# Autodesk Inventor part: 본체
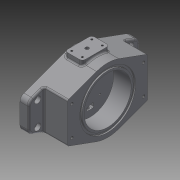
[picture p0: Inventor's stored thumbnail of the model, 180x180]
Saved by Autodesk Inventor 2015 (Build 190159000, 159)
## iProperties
Created: 2023-11
Part Number: 본체
Material: 알루미늄 6061
Document SubType Name: Modeling
Designer: user
Density: 2.7 g/cm^3
Appearance: 기본값
Mass: 1561.22 g
Surface Area: 721.057 cm^2
Volume: 578.228 cm^3
Author: user
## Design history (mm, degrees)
sketch "스케치2"
  geometry: L1 (18.811, 51.683)-(94, 24.317); L2 (94, 24.317)-(94, -24.317); L3 (18.811, -51.683)-(94, -24.317); L4 (0, 0)-(66.664, 0); L5 (0, 55)-(0, -55); L6 (-18.811, 51.683)-(-94, 24.317); L7 (-94, 24.317)-(-94, -24.317); L8 (-18.811, -51.683)-(-94, -24.317); A1 r 55 centre (0, 0) between (18.811, 51.683) and (-18.811, 51.683); A2 r 55 centre (0, 0) between (-18.811, -51.683) and (18.811, -51.683); 1 further point
  constraints: 16 end point, 6 point on circle, 4 symmetric about line, 2 centre point, 2 tangent, 2 vertical, 1 coincident, 1 horizontal, 1 other
  dimensions: "d3" = 94 distance from line of point (0, 0) L2; "d4" = 40 deg angle of L1 L3; "d5" = 55 radius of A1
extrude "돌출1" new body sketch "스케치2" distance "d6" = 15; taper "d7" = 0 deg
sketch "스케치4"
  geometry: L1 (-24.317, 94)-(-51.683, 18.811) reference; L2 (-51.683, -18.811)-(-24.317, -94) reference; L3 (-24.317, -94)-(24.317, -94) reference; L4 (51.683, 18.811)-(24.317, 94) reference; L5 (24.317, 94)-(-24.317, 94) reference; L6 (51.683, -18.811)-(24.317, -94) reference; L7 (-33.78, 68)-(33.78, 68); L8 (-33.78, 68)-(-51.683, 18.811); L9 (33.78, 68)-(51.683, 18.811); L10 (-33.78, -68)-(33.78, -68); L11 (-33.78, -68)-(-51.683, -18.811); L12 (-24.317, -94)-(-51.683, -18.811) reference; L13 (33.78, -68)-(51.683, -18.811); A1 r 55 centre (0, 0) between (-51.683, 18.811) and (-51.683, -18.811) reference; A2 r 55 centre (0, 0) between (51.683, -18.811) and (51.683, 18.811) reference; A3 r 55 centre (0, 0) between (-51.683, 18.811) and (-51.683, -18.811); A4 r 55 centre (0, 0) between (51.683, -18.811) and (51.683, 18.811)
  constraints: 13 end point, 4 point on circle, 4 point on line, 2 centre point, 2 horizontal, 2 parallel, 1 coincident, 1 collinear
  dimensions: "d13" = 68 distance from line of A1.centre L7; "d14" = 68 distance from line of A1.centre L10
extrude "돌출3" join sketch "스케치4" distance "d15" = 40; taper "d16" = 0 deg
sketch "스케치5"
  geometry: C1 r 40 at (0, 0); A1 r 55 centre (0, 0) between (51.683, -18.811) and (51.683, 18.811) reference
  constraints: 1 centre point, 1 coincident
  dimensions: "d17" = 80 diameter of C1
extrude "돌출4" cut sketch "스케치5" distance "d18" = 30; taper "d19" = 0 deg
node "작업 평면1"
sketch "스케치8"
  geometry: L1 (0, 18.811)-(0, -18.811) reference; L2 (10, -23)-(30, -23); L3 (35, -18)-(35, 18); L4 (30, 23)-(10, 23); L5 (5, 18)-(5, -18); L6 (5, -23)-(35, 23); L7 (35, -23)-(5, 23); L8 (0, 18.811)-(0, 94) reference; A1 r 5 centre (10, 18) between (10, 23) and (5, 18); A2 r 5 centre (30, 18) between (35, 18) and (30, 23); A3 r 5 centre (30, -18) between (30, -23) and (35, -18); A4 r 5 centre (10, -18) between (5, -18) and (10, -23); 4 further points
  constraints: 12 end point, 8 point on circle, 8 point on line, 8 tangent, 4 centre point, 4 midpoint, 3 equal radius, 2 parallel, 1 horizontal, 1 horizontal alignment, 1 perpendicular
  dimensions: "d31" = 30 distance of L6.end L7.end; "d32" = 46 distance of L7.end L6.start; "d33" = 20 distance from line of L8 point (20, 0); "d49" = 5 radius of A1
extrude "돌출6" join sketch "스케치8" stored distance "d34" = 20; taper "d35" = 0 deg
sketch "스케치9"
  geometry: C1 r 47.5 at (0, 0); C2 r 43.4 at (0, 0); A1 r 55 centre (0, 0) between (51.683, -18.811) and (51.683, 18.811) reference
  constraints: 2 centre point, 2 coincident
  dimensions: "d36" = 95 diameter of C1; "d37" = 4.1 radial gap between concentric circles of C1 C2
extrude "돌출7" cut sketch "스케치9" distance "d38" = 2.4; taper "d39" = 0 deg
sketch "스케치10"
  geometry: L1 (33.78, 68)-(-33.78, 68) reference; L2 (24.317, -94)-(-24.317, -94) reference; L3 (0, 0)-(0, 111.421); L4 (0, 0)-(71.748, 0); 4 further points
  constraints: 4 end point, 2 horizontal alignment, 2 symmetric about line, 2 vertical alignment, 1 horizontal, 1 vertical
  dimensions: "d40" = 158 distance of point (-20, -79) point (-20, 79); "d41" = 40 distance of point (20, -79) point (-20, -79)
hole "구멍2" sketch "스케치10" at (-20, 79), (20, 79), (-20, -79), (20, -79) diameter "d42" = 6.6; stored, may be unused: countersink angle "d46" = 90 deg, drill point angle "d48" = 0 deg; dims "d43" = 6, "d44" = 11, "d45" = 6.6, "d47" = 8
sketch "스케치11"
  geometry: L1 (0, 0)-(0, 104.924); L2 (0, 0)-(87.032, 0); C1 r 47.5 at (0, 0) reference; 4 further points
  constraints: 4 end point, 2 horizontal alignment, 2 symmetric about line, 2 vertical alignment, 1 horizontal, 1 vertical
  dimensions: "d50" = 50 distance of point (25, 61) point (-25, 61); "d51" = 122 distance of point (-25, -61) point (-25, 61)
hole "구멍3" sketch "스케치11" at (-25, 61), (25, 61), (-25, -61), (25, -61) diameter "d52" = 4.917; stored, may be unused: countersink angle "d56" = 90 deg, drill point angle "d58" = 118 deg; dims "d53" = 12, "d54" = 11, "d55" = 6.6, "d57" = 14
sketch "스케치12"
  geometry: L1 (40, 67.56)-(40, 0) reference; L2 (-15, 9.463)-(-15, 58.096) reference; 3 further points
  constraints: 1 horizontal alignment, 1 midpoint, 1 other
  dimensions: "d59" = 15 distance from line of L1 point (25, 33.78)
feature "엠보싱1" sketch "스케치12" dims "d60" = 0.5, "d61" = 0
fillet "모깎기1" dims "d71" = 10
fillet "모깎기2" dims "d72" = 3
fillet "모깎기3" dims "d73" = 3, "d75" = 0.5
sketch "스케치14"
  geometry: L1 (5, -18)-(5, 18) reference; L2 (5, 0)-(49.755, 0); L3 (10, 23)-(30, 23) reference; L4 (20, 23)-(20, -35.383); 5 further points
  constraints: 4 end point, 2 horizontal alignment, 2 midpoint, 2 symmetric about line, 2 vertical alignment, 1 horizontal, 1 vertical
  dimensions: "d76" = 34 distance of point (29, -17) point (29, 17); "d77" = 18 distance of point (29, 17) point (11, 17)
hole "구멍5" sketch "스케치14" at (11, 17), (29, 17), (11, -17), (29, -17) diameter "d78" = 3.242; stored, may be unused: countersink angle "d82" = 90 deg, drill point angle "d84" = 118 deg; dims "d79" = 8, "d80" = 11, "d81" = 6.6, "d83" = 10
sketch "스케치15"
  geometry: C1 r 17.5 at (0, -9); A1 r 55 centre (0, 0) between (51.683, -18.811) and (51.683, 18.811) reference; A2 r 55 centre (0, 0) between (-51.683, 18.811) and (-51.683, -18.811) reference
  constraints: 1 centre point, 1 vertical alignment
  dimensions: "d85" = 35 diameter of C1; "d86" = 9 distance of C1.centre A2.centre
extrude "돌출8" join sketch "스케치15" distance "d87" = 5; taper "d88" = 0 deg
sketch "스케치16"
  geometry: C1 r 17.5 at (0, 0) reference; 2 further points
  constraints: 1 coincident
hole "구멍6" sketch "스케치16" at (0, 0) diameter "d89" = 16; stored, may be unused: countersink angle "d93" = 90 deg, drill point angle "d95" = 0 deg; dims "d90" = 8, "d91" = 25, "d92" = 8.4, "d94" = 10
sketch "스케치17"
  geometry: C1 r 8 at (0, -9) reference; C2 r 10 at (0, -9)
  constraints: 1 centre point, 1 coincident
  dimensions: "d96" = 20 diameter of C2
extrude "돌출9" cut sketch "스케치17" distance "d97" = 10; taper "d98" = 0 deg
sketch "스케치18"
  geometry: L1 (0, 6)-(18.735, 6); L2 (0, -6)-(23.812, -6); L3 (0, 0)-(83.613, 0); L4 (18.735, 6)-(28.373, 6); L5 (23.812, -6)-(28.373, -6); L6 (28.373, -6)-(35.162, -6); L7 (28.373, 6)-(34.656, 6); C1 r 10 at (0, -9) reference; C2 r 40 at (0, 0) reference; A1 r 24 centre (0, -9) between (23.812, -6) and (18.735, 6); A2 r 29 centre (0, 0) between (28.373, -6) and (28.373, 6)
  constraints: 14 end point, 7 horizontal, 4 point on circle, 2 centre point, 2 coincident, 1 other
  dimensions: "d101" = 12 distance between parallel lines of L2 L1; "d102" = 24 radius of A1; "d103" = 29 radius of A2
extrude "돌출10" cut sketch "스케치18" distance "d104" = 12; taper "d105" = 0 deg
fillet "모깎기4" dims "d106" = 2
fillet "모깎기5" dims "d107" = 2
sketch "스케치19"
  geometry: L1 (0, 18.811)-(0, -18.811) reference; C1 r 3 at (20, 0); 2 further points
  constraints: 1 centre point, 1 horizontal alignment, 1 midpoint
  dimensions: "d108" = 6 diameter of C1; "d109" = 20 distance from line of L1 C1.centre
extrude "돌출11" cut sketch "스케치19" stored distance "d110" = 30; taper "d111" = 0 deg
fillet "모깎기6" dims "d112" = 0.2
chamfer "모따기1" distance "d113" = 0.4; stored, may be unused: second distance "d114" = 2, angle "d115" = 30 deg
chamfer "모따기2" distance "d116" = 1; stored, may be unused: second distance "d117" = 2, angle "d118" = 45 deg
sketch "스케치20"
  geometry: L1 (0, 0)-(0, 45.42); C1 r 40 at (0, 0) reference; A1 r 29 centre (0, 0) between (-28.68, 4.296) and (-28.68, -4.296) reference; 2 further points
  constraints: 2 end point, 1 symmetric about line, 1 vertical
  dimensions: "d119" = 30 distance of point (-15, 17) point (15, 17); "d120" = 17 vertical distance of A1.centre point (15, 17)
hole "구멍7" sketch "스케치20" at (-15, 17), (15, 17) diameter "d121" = 3.242; stored, may be unused: countersink angle "d125" = 90 deg, drill point angle "d127" = 118 deg; dims "d122" = 8, "d123" = 25, "d124" = 8.4, "d126" = 10
node "솔리드1"
mirror "대칭1"
mirror "대칭2"
mirror "대칭3"
mirror "대칭4"
other parameters: "d30" = 59, "d99" = 48, "d100" = 58
